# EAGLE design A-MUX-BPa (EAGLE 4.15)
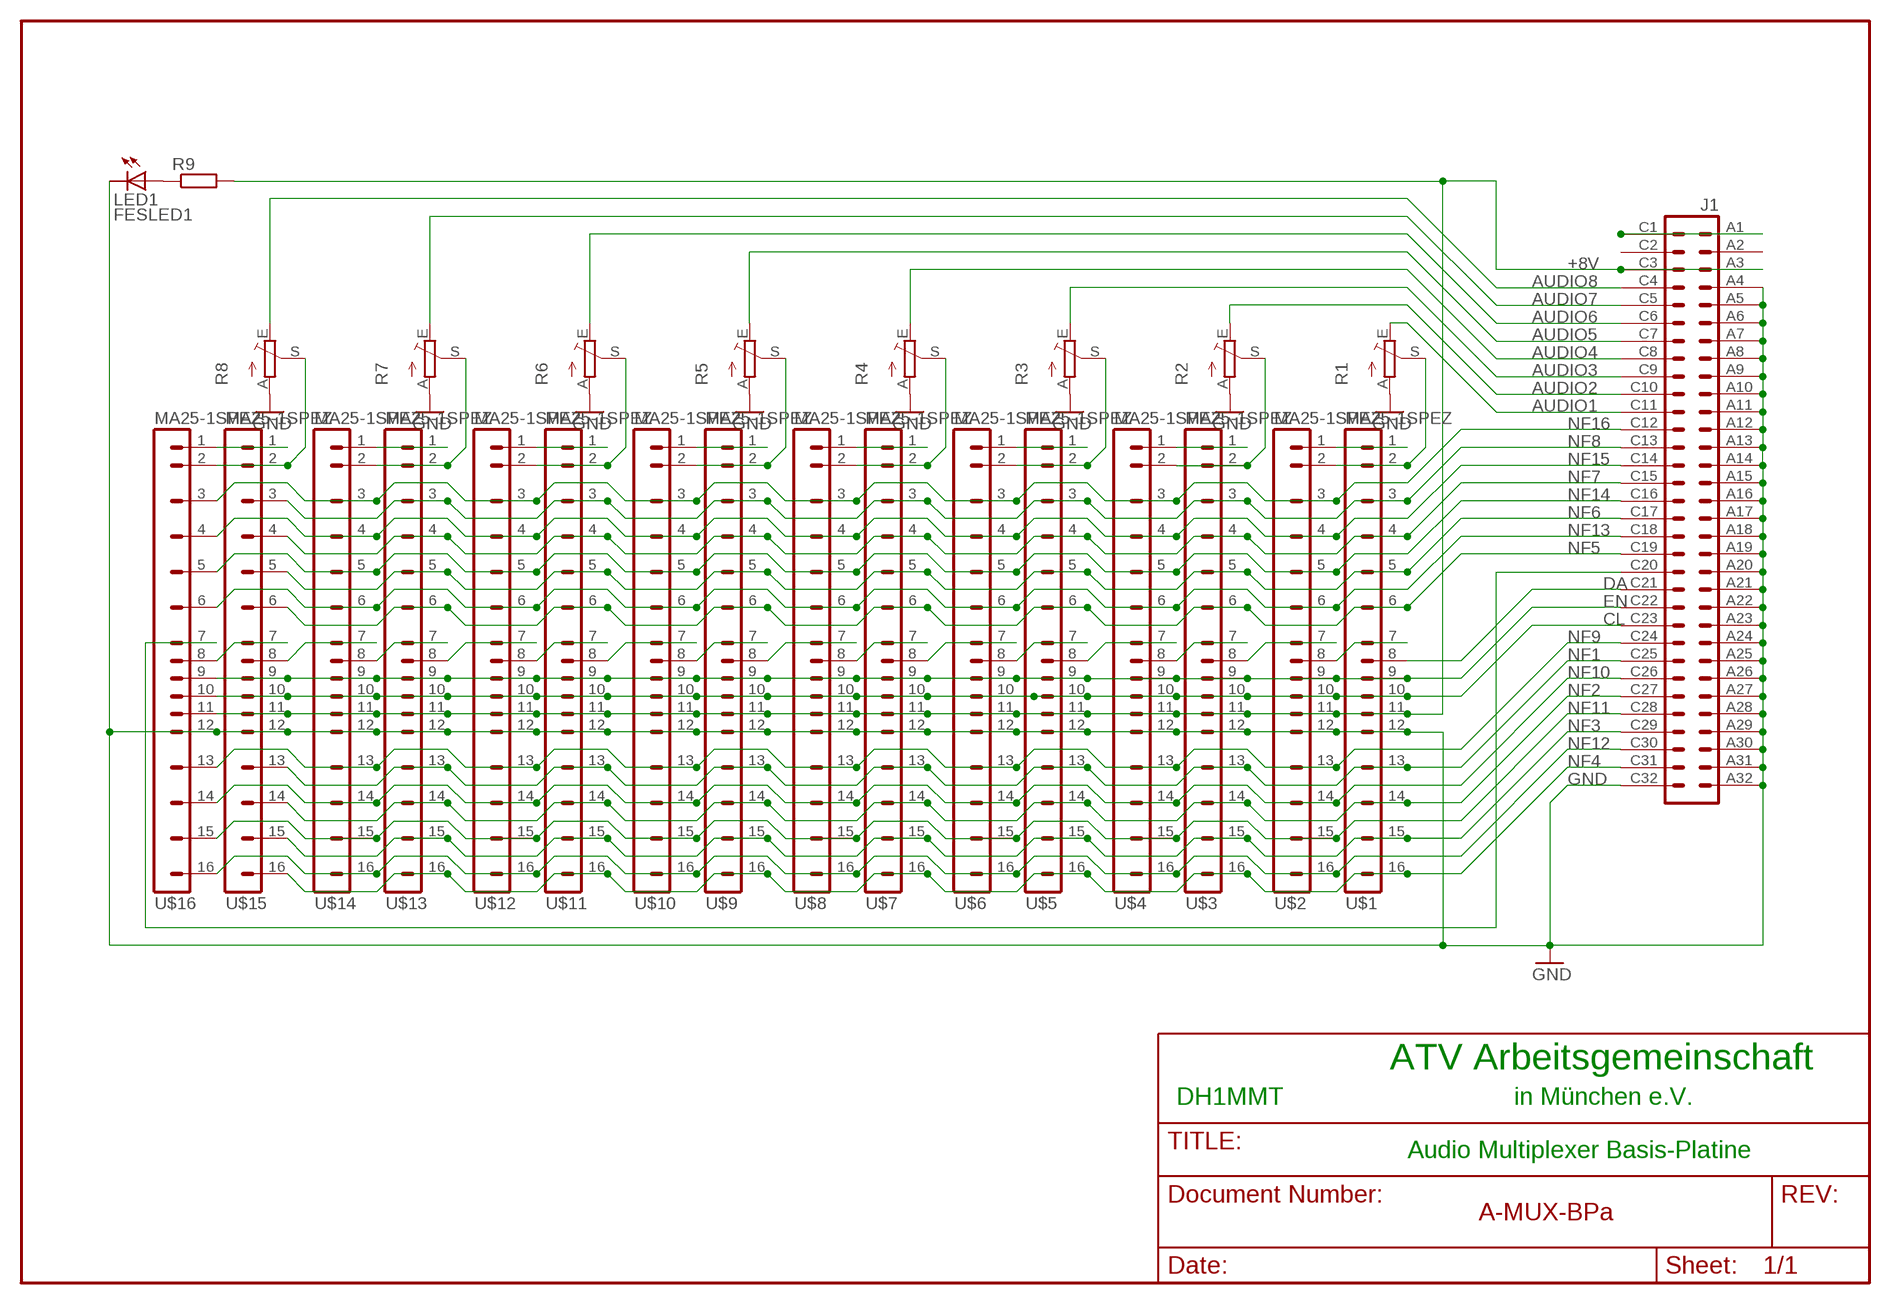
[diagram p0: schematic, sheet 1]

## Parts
J1  VG64  [VG64]
LED1  FESLED1  [FESLED1]
R1  TRIM_EU-B64W  [B64W]
R2  TRIM_EU-B64W  [B64W]
R3  TRIM_EU-B64W  [B64W]
R4  TRIM_EU-B64W  [B64W]
R5  TRIM_EU-B64W  [B64W]
R6  TRIM_EU-B64W  [B64W]
R7  TRIM_EU-B64W  [B64W]
R8  TRIM_EU-B64W  [B64W]
R9  R-EU_0204/7  [0204/7]
U$1  MA25-1SPEZ  [MA25-1SPEZ]
U$2  MA25-1SPEZ  [MA25-1SPEZ]
U$3  MA25-1SPEZ  [MA25-1SPEZ]
U$4  MA25-1SPEZ  [MA25-1SPEZ]
U$5  MA25-1SPEZ  [MA25-1SPEZ]
U$6  MA25-1SPEZ  [MA25-1SPEZ]
U$7  MA25-1SPEZ  [MA25-1SPEZ]
U$8  MA25-1SPEZ  [MA25-1SPEZ]
U$9  MA25-1SPEZ  [MA25-1SPEZ]
U$10  MA25-1SPEZ  [MA25-1SPEZ]
U$11  MA25-1SPEZ  [MA25-1SPEZ]
U$12  MA25-1SPEZ  [MA25-1SPEZ]
U$13  MA25-1SPEZ  [MA25-1SPEZ]
U$14  MA25-1SPEZ  [MA25-1SPEZ]
U$15  MA25-1SPEZ  [MA25-1SPEZ]
U$16  MA25-1SPEZ  [MA25-1SPEZ]

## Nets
+8V: J1.A3 J1.C3 R9.2 U$1.11 U$2.11 U$3.11 U$4.11 U$5.11 U$6.11 U$7.11 U$8.11 U$9.11 U$10.11 U$11.11 U$12.11 U$13.11 U$14.11 U$15.11 U$16.11
+12V: J1.A1 J1.C1
AUDIO1: J1.C11 R1.E
AUDIO2: J1.C10 R2.E
AUDIO3: J1.C9 R3.E
AUDIO4: J1.C8 R4.E
AUDIO5: J1.C7 R5.E
AUDIO6: J1.C6 R6.E
AUDIO7: J1.C5 R7.E
AUDIO8: J1.C4 R8.E
CL: J1.C23 U$1.10 U$2.10 U$3.10 U$4.10 U$5.10 U$6.10 U$7.10 U$8.10 U$9.10 U$10.10 U$11.10 U$12.10 U$13.10 U$14.10 U$15.10 U$16.10
DA: J1.C21 U$1.8
EN: J1.C22 U$1.9 U$2.9 U$3.9 U$4.9 U$5.9 U$6.9 U$7.9 U$8.9 U$9.9 U$10.9 U$11.9 U$12.9 U$13.9 U$14.9 U$15.9 U$16.9
GND: J1.A4 J1.A5 J1.A6 J1.A7 J1.A8 J1.A9 J1.A10 J1.A11 J1.A12 J1.A13 J1.A14 J1.A15 J1.A16 J1.A17 J1.A18 J1.A19 J1.A20 J1.A21 J1.A22 J1.A23 J1.A24 J1.A25 J1.A26 J1.A27 J1.A28 J1.A29 J1.A30 J1.A31 J1.A32 J1.C32 LED1.K(C) R1.A R2.A R3.A R4.A R5.A R6.A R7.A R8.A U$1.12 U$2.12 U$3.12 U$4.12 U$5.12 U$6.12 U$7.12 U$8.12 U$9.12 U$10.12 U$11.12 U$12.12 U$13.12 U$14.12 U$15.12 U$16.12
N$1: J1.C20 U$16.7
N$4: U$1.1 U$2.1
N$5: U$3.1 U$4.1
N$8: U$5.1 U$6.1
N$10: U$7.1 U$8.1
N$11: LED1.A R9.1
N$13: U$15.1 U$16.1
N$15: U$13.1 U$14.1
N$17: U$11.1 U$12.1
N$34: U$9.1 U$10.1
N$35: R5.S U$9.2 U$10.2
N$40: U$1.7 U$2.8
N$43: U$2.7 U$3.8
N$67: U$3.7 U$4.8
N$68: U$4.7 U$5.8
N$69: U$5.7 U$6.8
N$70: U$6.7 U$7.8
N$71: U$7.7 U$8.8
N$72: U$8.7 U$9.8
N$73: U$9.7 U$10.8
N$74: U$10.7 U$11.8
N$75: U$11.7 U$12.8
N$76: U$12.7 U$13.8
N$77: U$13.7 U$14.8
N$78: U$14.7 U$15.8
N$79: U$15.7 U$16.8
N$98: R2.S U$3.2 U$4.2
N$99: R1.S U$1.2 U$2.2
N$103: R3.S U$5.2 U$6.2
N$104: R4.S U$7.2 U$8.2
N$106: R6.S U$11.2 U$12.2
N$107: R7.S U$13.2 U$14.2
N$108: R8.S U$15.2 U$16.2
NF1: J1.C25 U$1.13 U$3.13 U$5.13 U$7.13 U$9.13 U$11.13 U$13.13 U$15.13
NF2: J1.C27 U$1.14 U$3.14 U$5.14 U$7.14 U$9.14 U$11.14 U$13.14 U$15.14
NF3: J1.C29 U$1.15 U$3.15 U$5.15 U$7.15 U$9.15 U$11.15 U$13.15 U$15.15
NF4: J1.C31 U$1.16 U$3.16 U$5.16 U$7.16 U$9.16 U$11.16 U$13.16 U$15.16
NF5: J1.C19 U$1.6 U$3.6 U$5.6 U$7.6 U$9.6 U$11.6 U$13.6 U$15.6
NF6: J1.C17 U$1.5 U$3.5 U$5.5 U$7.5 U$9.5 U$11.5 U$13.5 U$15.5
NF7: J1.C15 U$1.4 U$3.4 U$5.4 U$7.4 U$9.4 U$11.4 U$13.4 U$15.4
NF8: J1.C13 U$1.3 U$3.3 U$5.3 U$7.3 U$9.3 U$11.3 U$13.3 U$15.3
NF9: J1.C24 U$2.13 U$4.13 U$6.13 U$8.13 U$10.13 U$12.13 U$14.13 U$16.13
NF10: J1.C26 U$2.14 U$4.14 U$6.14 U$8.14 U$10.14 U$12.14 U$14.14 U$16.14
NF11: J1.C28 U$2.15 U$4.15 U$6.15 U$8.15 U$10.15 U$12.15 U$14.15 U$16.15
NF12: J1.C30 U$2.16 U$4.16 U$6.16 U$8.16 U$10.16 U$12.16 U$14.16 U$16.16
NF13: J1.C18 U$2.6 U$4.6 U$6.6 U$8.6 U$10.6 U$12.6 U$14.6 U$16.6
NF14: J1.C16 U$2.5 U$4.5 U$6.5 U$8.5 U$10.5 U$12.5 U$14.5 U$16.5
NF15: J1.C14 U$2.4 U$4.4 U$6.4 U$8.4 U$10.4 U$12.4 U$14.4 U$16.4
NF16: J1.C12 U$2.3 U$4.3 U$6.3 U$8.3 U$10.3 U$12.3 U$14.3 U$16.3
Unconnected: J1.A2 J1.C2

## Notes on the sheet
- ATV Arbeitsgemeinschaft
- DH1MMT | in München e.V.
- Audio Multiplexer Basis-Platine

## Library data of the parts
J1 = 19inch:VG64: PCB EUROCARD, 64-pin type C/AC, 2.54 mm
LED1 = led:FESLED1
R1-R8 = pot:TRIM_EU-: POTENTIOMETER
R9 = rcl:R-EU_: RESISTOR, European symbol
U$1-U$16 = con-lstb:MA25-1SPEZ

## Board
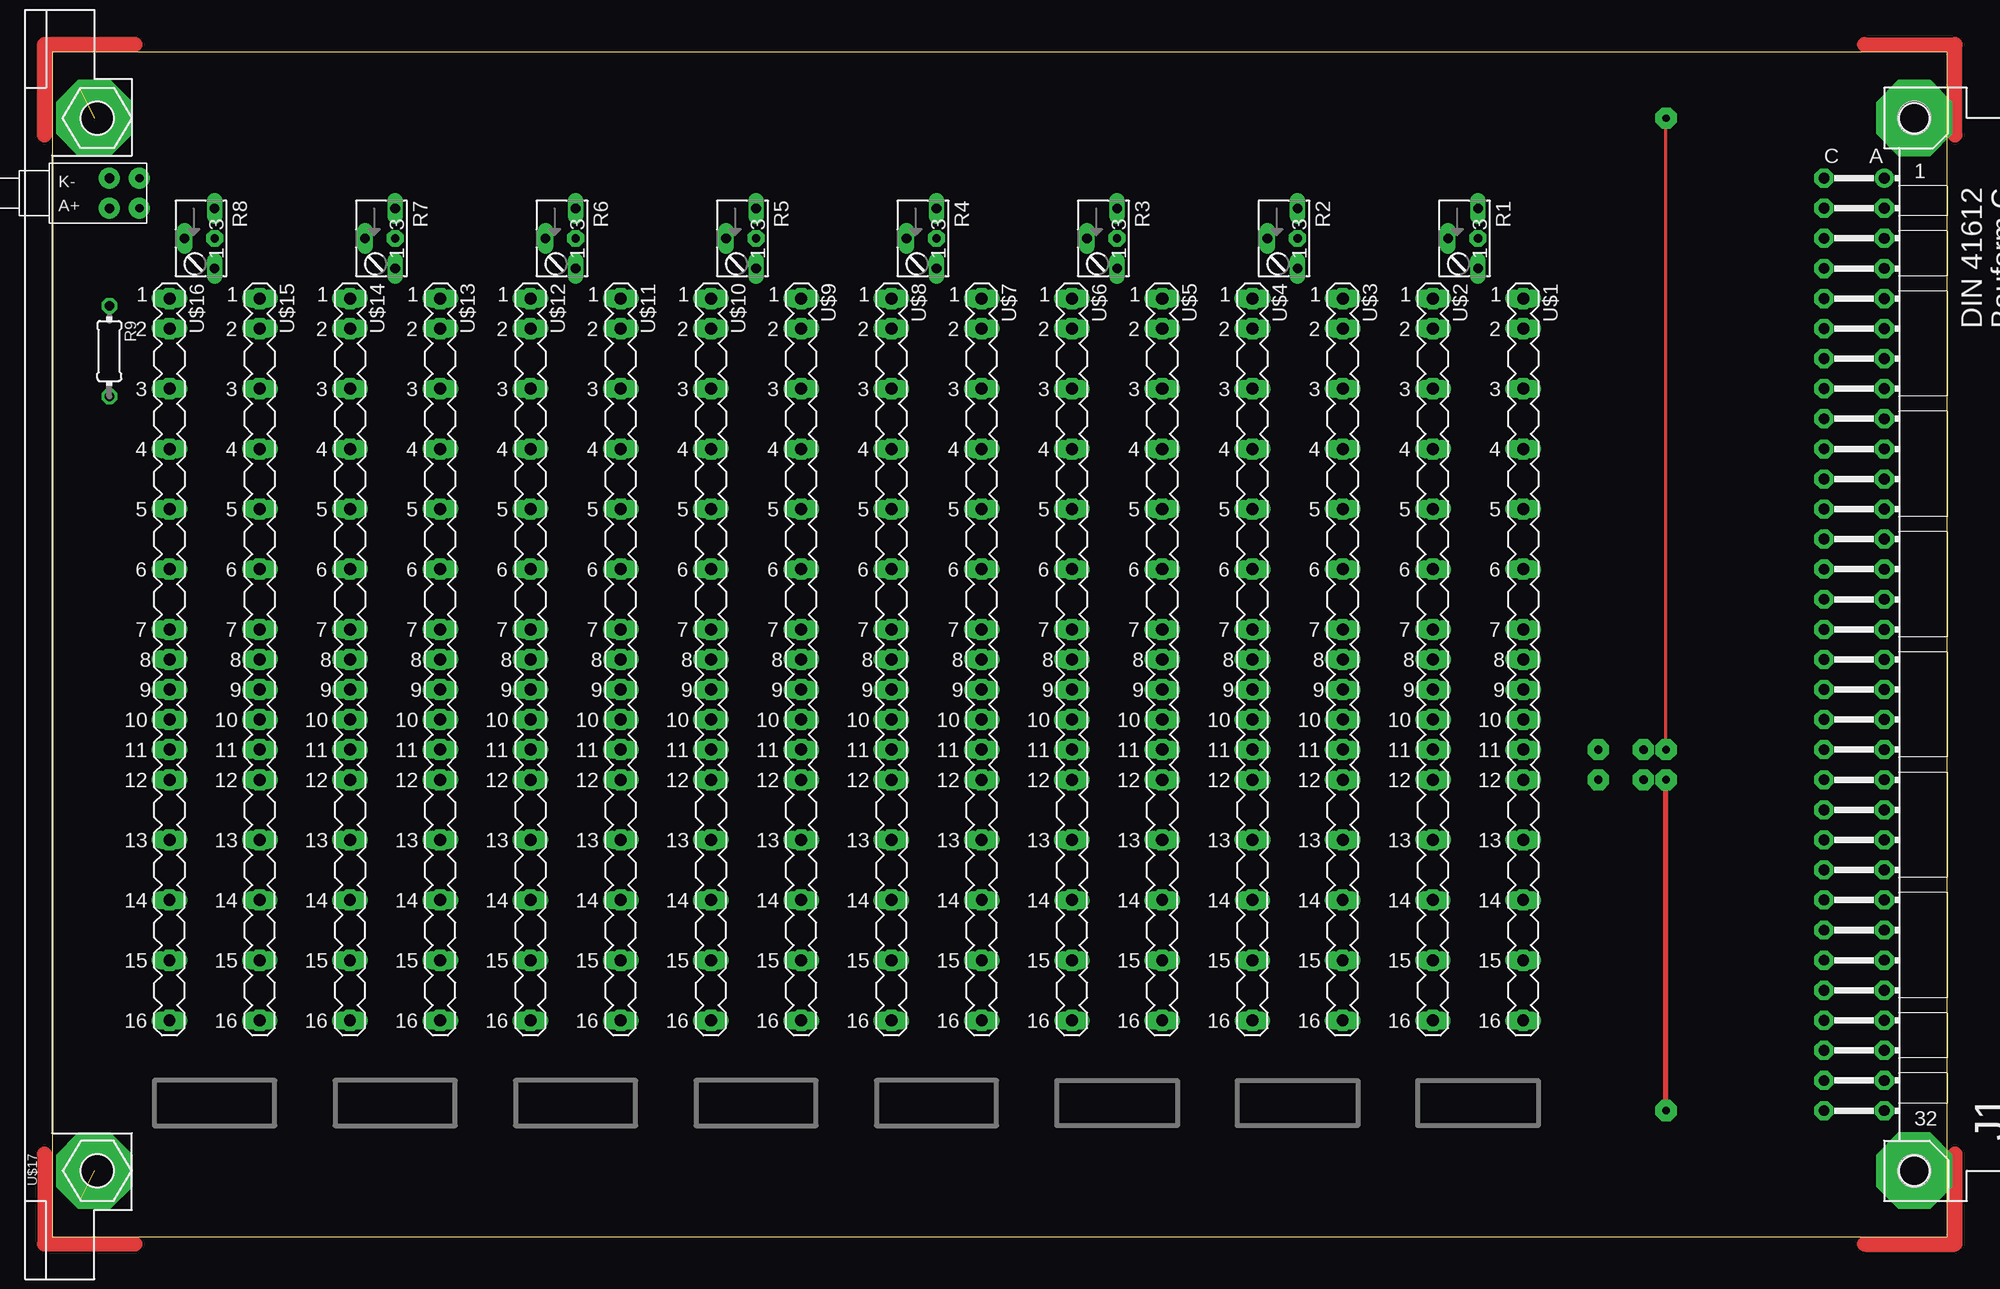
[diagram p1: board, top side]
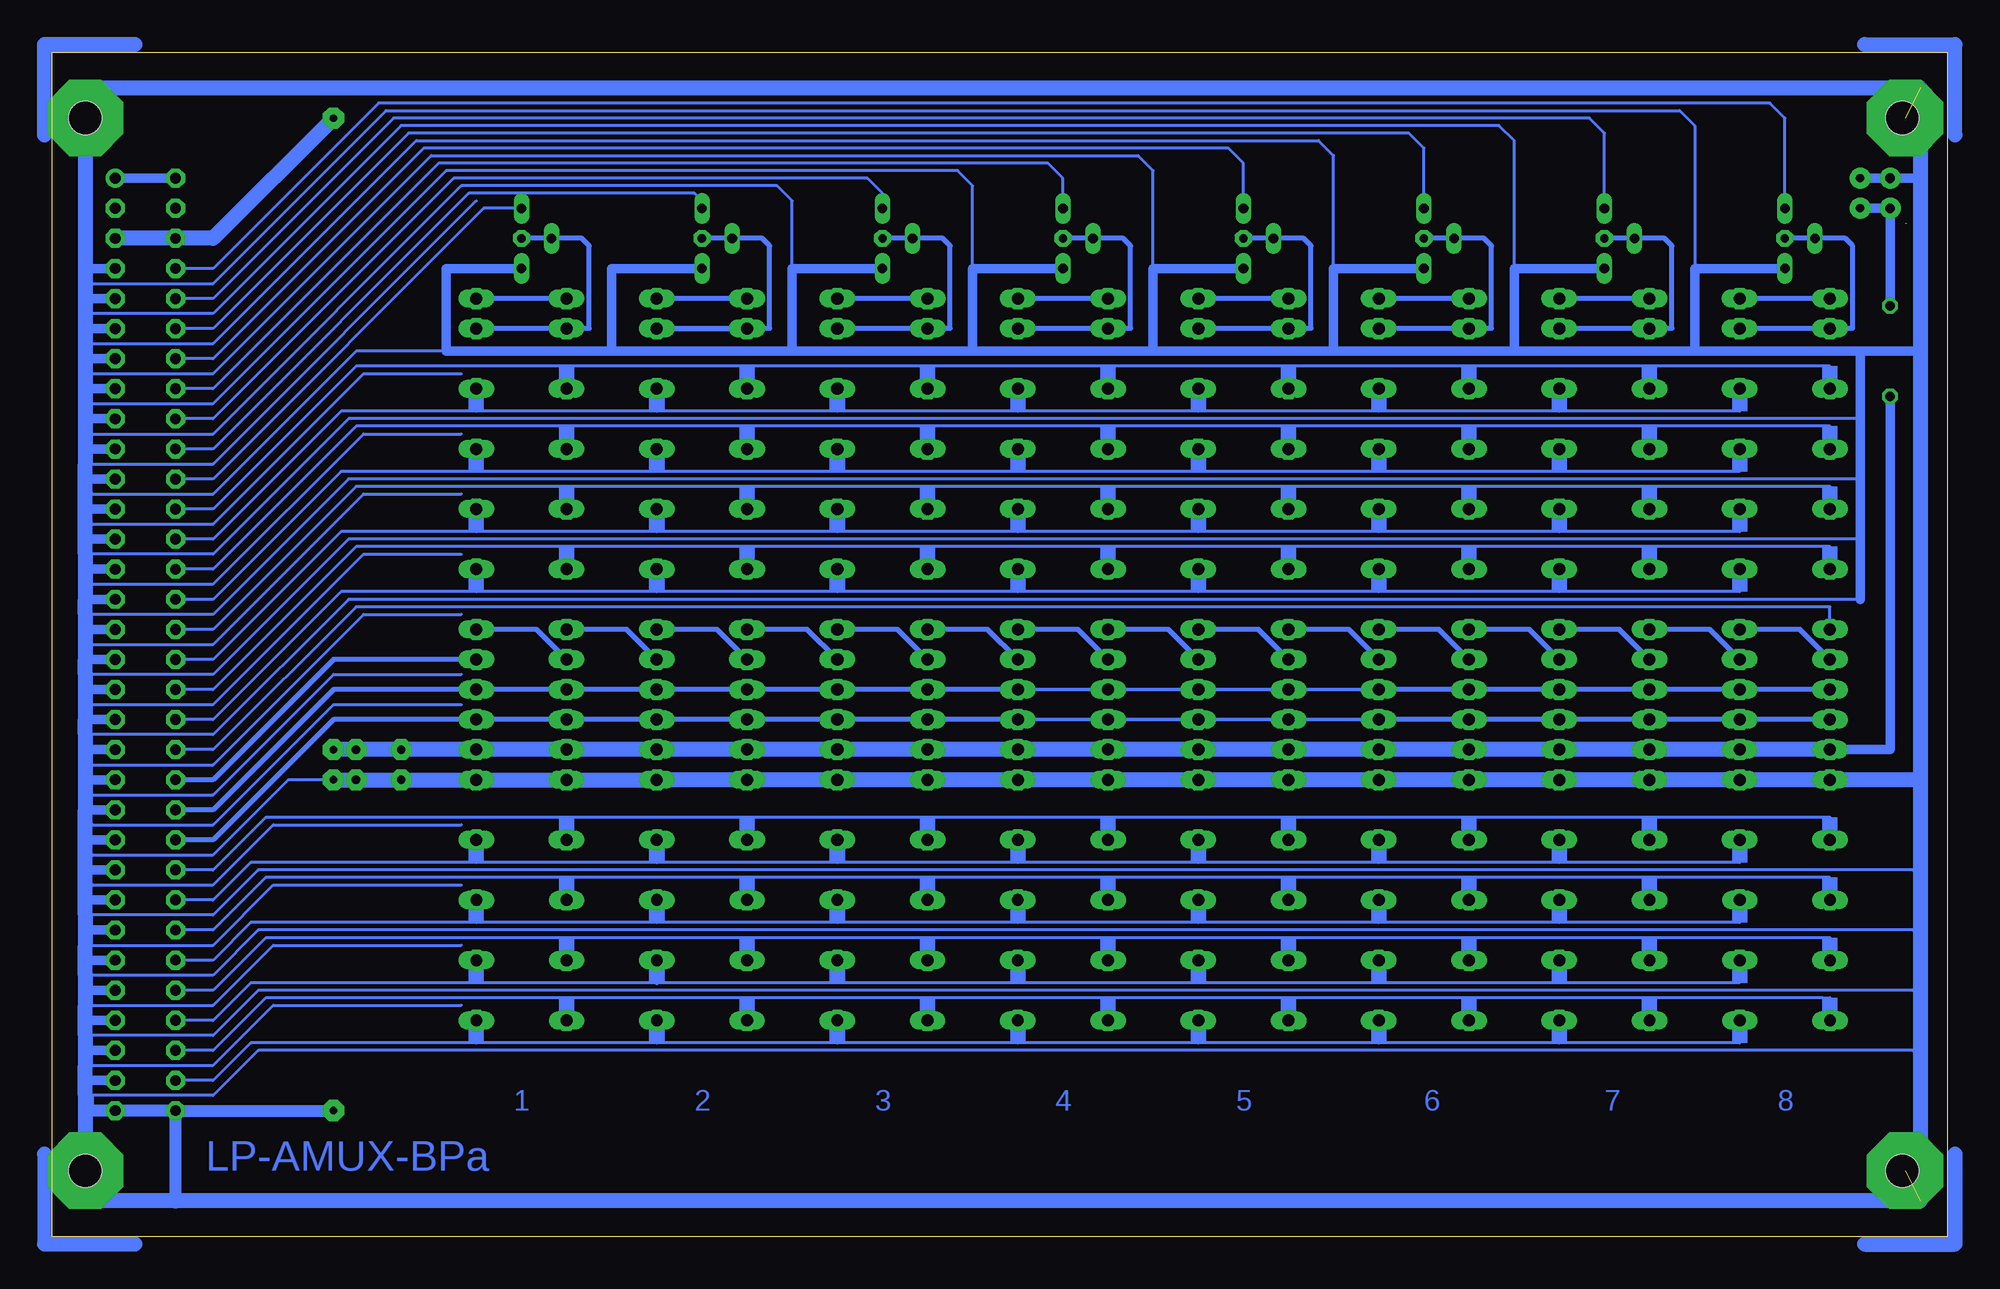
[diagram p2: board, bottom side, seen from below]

Size 160.02 x 100.03 mm. Coordinates in mm from the lower left corner, seen from the top.
Copper layers (1*16): Top 0.035mm / dielectric 1.5mm / Bottom 0.035mm
Design rules "default": minimum track width 10mil, minimum drill 24mil, track to track 8mil, track to pad 8mil, pad to pad 8mil, via to via 8mil, smd to smd 8mil, copper to edge 40mil, drill to drill 8mil, minimum pad ring 10mil, minimum via ring 8mil, stop-mask expansion 4mil, vias tented up to drill 0mil, thermal gap 10mil

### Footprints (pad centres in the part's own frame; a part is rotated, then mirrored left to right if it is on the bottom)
VG64 = drill 0.914 pad 1.6 round: A1 154.94,39.37 | drill 0.914 pad 1.6 octagon: A2 154.94,36.83; A3 154.94,34.29; A4 154.94,31.75; A5 154.94,29.21; A6 154.94,26.67; A7 154.94,24.13; A8 154.94,21.59; A9 154.94,19.05; A10 154.94,16.51; A11 154.94,13.97; A12 154.94,11.43; A13 154.94,8.89; A14 154.94,6.35; A15 154.94,3.81; A16 154.94,1.27; A17 154.94,-1.27; A18 154.94,-3.81; A19 154.94,-6.35; A20 154.94,-8.89; A21 154.94,-11.43; A22 154.94,-13.97; A23 154.94,-16.51; A24 154.94,-19.05; A25 154.94,-21.59; A26 154.94,-24.13; A27 154.94,-26.67; A28 154.94,-29.21; A29 154.94,-31.75; A30 154.94,-34.29; A31 154.94,-36.83; A32 154.94,-39.37; C1 149.86,39.37; C2 149.86,36.83; C3 149.86,34.29; C4 149.86,31.75; C5 149.86,29.21; C6 149.86,26.67; C7 149.86,24.13; C8 149.86,21.59; C9 149.86,19.05; C10 149.86,16.51; C11 149.86,13.97; C12 149.86,11.43; C13 149.86,8.89; C14 149.86,6.35; C15 149.86,3.81; C16 149.86,1.27; C17 149.86,-1.27; C18 149.86,-3.81; C19 149.86,-6.35; C20 149.86,-8.89; C21 149.86,-11.43; C22 149.86,-13.97; C23 149.86,-16.51; C24 149.86,-19.05; C25 149.86,-21.59; C26 149.86,-24.13; C27 149.86,-26.67; C28 149.86,-29.21; C29 149.86,-31.75; C30 149.86,-34.29; C31 149.86,-36.83; C32 149.86,-39.37 | hole 2.794: 157.48,44.45; 157.48,-44.45
FESLED1 = drill 0.813 pad 1.778 round: A 5.08,-1.27; A1 5.08,-1.27; K 5.08,1.27; K1 5.08,1.27
B64W = drill 0.813 long: A 2.54,0; E -2.54,0; S 0,-2.54
0204/7 = drill 0.813 octagon: 1 -3.81,0; 2 3.81,0
MA25-1SPEZ = drill 1.016 long: 1 0,27.94; 2 0,25.4; 3 0,20.32; 4 0,15.24; 5 0,10.16; 6 0,5.08; 7 0,0; 8 0,-2.54; 9 0,-5.08; 10 0,-7.62; 11 0,-10.16; 12 0,-12.7; 13 0,-17.78 | drill 1 long: 14 0,-22.86; 15 0,-27.94; 16 0,-33.02
FPH = hole 2.794: 3.81,44.45; 3.81,-44.45

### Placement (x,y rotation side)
E$1  [DINA4_L]  not placed on the board
J1  -0.25,50.01 0 top
LED1  -0.25,88.11 0 top
R1  120.4,84.3 270 top
R2  105.16,84.3 270 top
R3  89.92,84.3 270 top
R4  74.68,84.3 270 top
R5  59.44,84.3 270 top
R6  44.2,84.3 270 top
R7  28.96,84.3 270 top
R8  13.72,84.3 270 top
R9  4.83,74.78 270 top
U$1  124.21,51.28 0 top
U$2  116.59,51.28 0 top
U$3  108.97,51.28 0 top
U$4  101.35,51.28 0 top
U$5  93.73,51.28 0 top
U$6  86.11,51.28 0 top
U$7  78.49,51.28 0 top
U$8  70.87,51.28 0 top
U$9  63.25,51.28 0 top
U$10  55.63,51.28 0 top
U$11  48.01,51.28 0 top
U$12  40.39,51.28 0 top
U$13  32.77,51.28 0 top
U$14  25.15,51.28 0 top
U$15  17.53,51.28 0 top
U$16  9.91,51.28 0 top
U$17  [FPH]  0,50.01 0 top

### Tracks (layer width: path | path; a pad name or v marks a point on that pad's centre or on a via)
+8V  (via drill 0.6 pad 1.78, 0.7 pad 1.78, 0.9 pad 1.78)
  Top 0.254: v136.27,41.12 v136.27,94.46
  Bottom 0.813: U$16.11 4.83,41.12 R9.2
  Bottom 1.27: J1.A3 J1.C3 146.43,84.3 v136.27,94.46 | U$16.11 U$15.11 U$14.11 U$13.11 U$12.11 U$11.11 U$10.11 U$9.11 U$8.11 U$7.11 U$6.11 U$5.11 U$4.11 U$3.11 U$2.11 U$1.11 v130.56,41.12 v134.37,41.12 v136.27,41.12
  other vias: 78.49,41.12 86.11,41.12 93.73,41.12 124.21,41.12 116.59,41.12 101.35,41.12 108.97,41.12 9.91,41.12 17.53,41.12 25.15,41.12 32.77,41.12 40.39,41.12 48.01,41.12
+12V
  Bottom 0.813: J1.C1 J1.A1
AUDIO1
  Bottom 0.254: J1.C11 146.43,63.98 123.57,86.84 R1.E
AUDIO2
  Bottom 0.254: J1.C10 146.43,66.52 124.84,88.11 105.79,88.11 105.16,87.48 R2.E
AUDIO3
  Bottom 0.254: J1.C9 146.43,69.06 126.11,89.38 91.19,89.38 89.92,88.11 R3.E
AUDIO4
  Bottom 0.254: J1.C8 146.43,71.6 127.38,90.65 75.95,90.65 74.68,89.38 R4.E
AUDIO5
  Bottom 0.254: J1.C7 146.43,74.14 128.65,91.92 60.71,91.92 59.44,90.65 R5.E
AUDIO6
  Bottom 0.254: J1.C6 146.43,76.68 129.92,93.19 45.47,93.19 44.2,91.92 R6.E
AUDIO7
  Bottom 0.254: R7.E 28.96,93.19 30.23,94.46 131.19,94.46 146.43,79.22 J1.C5
AUDIO8
  Bottom 0.254: J1.C4 146.43,81.76 132.46,95.73 14.99,95.73 13.72,94.46 R8.E
CL
  Bottom 0.305: U$7.10 U$8.10 U$9.10 U$10.10 U$11.10
  Bottom 0.406: J1.C23 146.43,33.5 136.27,43.66 U$1.10 U$2.10 U$3.10 U$4.10 U$5.10 U$6.10 U$7.10 | U$11.10 U$12.10 U$13.10 U$14.10 U$15.10 U$16.10
DA  (via drill 0.9 pad 1.78)
  Bottom 0.406: U$1.8 136.27,48.74 146.43,38.58 J1.C21
  other vias: 124.21,48.74
EN  (via drill 0.9 pad 1.78)
  Bottom 0.305: U$7.9 U$8.9 U$9.9 U$10.9 U$11.9
  Bottom 0.406: J1.C22 146.43,36.04 136.27,46.2 U$1.9 U$2.9 U$3.9 U$4.9 U$5.9 U$6.9 U$7.9 | U$11.9 U$12.9 U$13.9 U$14.9 U$15.9 U$16.9
  other vias: 124.21,46.2 116.59,46.2 108.97,46.2 93.73,46.2 101.35,46.2
GND  (via drill 0.6 pad 1.78, 0.6 pad 6.45, 0.7 pad 1.78, 0.9 pad 1.78)  (2 unrouted)
  Top 0.406: v136.27,10.64 v136.27,38.58
  Bottom 0.254: 157.23,80.49 146.43,80.49 131.83,95.1 22.61,95.1 21.34,93.83 21.34,81.76 | 157.23,75.41 146.43,75.41 129.29,92.56 53.09,92.56 51.82,91.29 51.82,81.76 | 67.06,81.76 67.06,90.02 68.33,91.29 128.02,91.29 146.43,72.87 157.23,72.87 157.23,70.33 146.43,70.33 126.75,90.02 83.57,90.02 82.3,88.75 82.3,81.76 | 157.23,67.79 146.43,67.79 125.48,88.75 98.81,88.75 97.54,87.48 97.54,81.76 | 157.23,62.71 146.43,62.71 134.37,74.78 126.75,74.78 | 36.58,81.76 36.58,92.56 37.85,93.83 130.56,93.83 146.43,77.95 156.59,77.95 | 157.23,57.63 146.43,57.63 135,69.06 7.37,69.06 | 157.23,52.55 146.43,52.55 135,63.98 7.37,63.98 | 157.23,47.47 146.43,47.47 135,58.9 7.37,58.9 | 7.37,53.82 135,53.82 146.43,42.39 157.23,42.39 | 157.23,32.23 146.43,32.23 140.08,38.58 v136.27,38.58 | 157.23,27.15 146.43,27.15 142.62,30.96 2.29,30.96 | 2.29,25.88 142.62,25.88 146.43,22.07 157.23,22.07 | 157.23,16.99 146.43,16.99 142.62,20.8 2.29,20.8 | 157.23,65.25 146.43,65.25 124.21,87.48 | 156.59,10.64 156.59,11.91 | 157.23,60.17 146.43,60.17 133.73,72.87 125.48,72.87 | 157.23,55.09 146.43,55.09 133.73,67.79 125.48,67.79 | 157.23,50.01 146.43,50.01 133.73,62.71 125.48,62.71 | 157.23,44.93 146.43,44.93 133.73,57.63 125.48,57.63 | 157.23,39.85 146.43,39.85 133.73,52.55 125.48,52.55 | 157.23,37.31 146.43,37.31 136.27,47.47 125.48,47.47 | 157.23,34.77 146.43,34.77 136.27,44.93 125.48,44.93 | 157.23,24.61 146.43,24.61 141.35,29.69 125.48,29.69 | 157.23,19.53 146.43,19.53 141.35,24.61 125.48,24.61 | 157.23,14.45 146.43,14.45 141.35,19.53 125.48,19.53 | 157.23,11.91 146.43,11.91 142.62,15.72 2.29,15.72 | 157.23,29.69 146.43,29.69 141.35,34.77 125.48,34.77
  Bottom 0.813: 157.23,46.2 J1.A18 | 157.23,48.74 J1.A17 | 157.23,51.28 J1.A16 | 157.23,43.66 J1.A19 | 157.23,41.12 J1.A20 | 157.23,53.82 J1.A15 | 157.23,56.36 J1.A14 | 157.23,38.58 J1.A21 | 157.23,36.04 J1.A22 | 157.23,58.9 J1.A13 | 157.23,61.44 J1.A12 | 157.23,33.5 J1.A23 | 157.23,30.96 J1.A24 | 157.23,63.98 J1.A11 | 157.23,66.52 J1.A10 | 157.23,28.42 J1.A25 | 157.23,25.88 J1.A26 | 157.23,69.06 J1.A9 | 157.23,71.6 J1.A8 | 157.23,23.34 J1.A27 | 157.23,20.8 J1.A28 | 157.23,74.14 J1.A7 | 157.23,76.68 J1.A6 | 157.23,18.26 J1.A29 | 157.23,15.72 J1.A30 | 157.23,79.22 J1.A5 | 157.23,81.76 J1.A4 | 157.23,13.18 J1.A31 | 21.34,74.78 21.34,81.76 R8.A | 51.82,74.78 51.82,81.76 R6.A | 67.06,74.78 67.06,81.76 R5.A | 82.3,74.78 82.3,81.76 R4.A | 97.54,74.78 97.54,81.76 R3.A | 112.78,74.78 126.75,74.78 126.75,81.76 R1.A | 97.54,74.78 112.78,74.78 | 82.3,74.78 97.54,74.78 | 67.06,74.78 82.3,74.78 | 51.82,74.78 67.06,74.78 | 36.58,74.78 36.58,81.76 R7.A | 36.58,74.78 51.82,74.78 | 21.34,74.78 36.58,74.78 | 7.37,74.78 7.37,69.06 7.37,63.98 7.37,58.9 7.37,53.82 | 7.37,74.78 21.34,74.78 | 112.78,74.78 112.78,81.76 R2.A | 2.29,89.38 LED1.K v7.37,89.38 | 2.29,74.78 7.37,74.78
  Bottom 1.016: J1.C32 J1.A32 156.59,10.64 157.23,10.64 | 149.61,3.02 J1.C32 | J1.C32 v136.27,10.64
  Bottom 1.27: 2.29,38.58 2.29,74.78 2.29,89.38 2.29,97 157.23,97 v157.23,94.46 157.23,81.76 157.23,80.49 157.23,79.22 157.23,76.68 157.23,75.41 157.23,74.14 157.23,72.87 157.23,71.6 157.23,70.33 157.23,69.06 157.23,67.79 157.23,66.52 157.23,65.25 157.23,63.98 157.23,62.71 157.23,61.44 157.23,60.17 157.23,58.9 157.23,57.63 157.23,56.36 157.23,55.09 157.23,53.82 157.23,52.55 157.23,51.28 157.23,50.01 157.23,48.74 157.23,47.47 157.23,46.2 157.23,44.93 157.23,43.66 157.23,42.39 157.23,41.12 157.23,39.85 157.23,38.58 157.23,37.31 157.23,36.04 157.23,34.77 157.23,33.5 157.23,32.23 157.23,30.96 157.23,29.69 157.23,28.42 157.23,27.15 157.23,25.88 157.23,24.61 157.23,23.34 157.23,22.07 157.23,20.8 157.23,19.53 157.23,18.26 157.23,16.99 157.23,15.72 157.23,14.45 157.23,13.18 157.23,11.91 157.23,10.64 v157.23,5.56 157.23,3.02 149.61,3.02 2.29,3.02 2.29,15.72 2.29,20.8 2.29,25.88 2.29,30.96 2.29,38.58 | v136.27,38.58 v134.37,38.58 v130.56,38.58 U$1.12 U$2.12 U$3.12 U$4.12 U$5.12 U$6.12 U$7.12 U$8.12 U$9.12 U$10.12 U$11.12 U$12.12 U$13.12 U$14.12 U$15.12 U$16.12 2.29,38.58
  other vias: 124.21,38.58 116.59,38.58 108.97,38.58 101.35,38.58 93.73,38.58 86.11,38.58 78.49,38.58 48.01,38.58 40.39,38.58 32.77,38.58 25.15,38.58 17.53,38.58 9.91,38.58 70.87,38.58 63.25,38.58 3.56,94.46 3.56,5.56
N$1  (via drill 0.9 pad 1.78)
  Bottom 0.254: U$16.7 9.91,53.19 134.37,53.19 146.43,41.12 J1.C20
  other vias: 9.91,51.28
N$2
  Bottom 0: 3.56,85.57 3.43,85.57
N$4
  Bottom 0.254: U$2.1 U$1.1
N$5
  Bottom 0.254: U$4.1 U$3.1
N$8
  Bottom 0.254: U$6.1 U$5.1
N$10
  Bottom 0.254: U$8.1 U$7.1
N$11  (via drill 0.7 pad 1.78)
  Bottom 0.813: R9.1 LED1.A v7.37,86.84
N$13
  Bottom 0.254: U$16.1 U$15.1
N$15
  Bottom 0.406: U$14.1 U$13.1
N$17
  Bottom 0.254: U$12.1 U$11.1
N$18  (via drill 0.9 pad 1.78)
  other vias: 63.25,41.12
N$19  (via drill 0.9 pad 1.78)
  other vias: 70.87,43.66
N$20  (via drill 0.9 pad 1.78)
  other vias: 78.49,46.2
N$21  (via drill 0.9 pad 1.78)
  other vias: 55.63,23.34
N$24  (via drill 0.9 pad 1.78)
  other vias: 63.25,28.42
N$25  (via drill 0.9 pad 1.78)
  other vias: 108.97,43.66
N$26  (via drill 0.9 pad 1.78)
  other vias: 116.59,43.66
N$27  (via drill 0.9 pad 1.78)
  other vias: 70.87,28.42
N$28  (via drill 0.9 pad 1.78)
  other vias: 70.87,23.34
N$29  (via drill 0.9 pad 1.78)
  other vias: 70.87,18.26
N$30  (via drill 0.9 pad 1.78)
  other vias: 55.63,18.26
N$31  (via drill 0.9 pad 1.78)
  other vias: 124.21,43.66
N$32  (via drill 0.9 pad 1.78)
  other vias: 101.35,43.66
N$33  (via drill 0.9 pad 1.78)
  other vias: 93.73,43.66
N$34
  Bottom 0.254: U$10.1 U$9.1
N$35  (via drill 0.7 pad 1.42)
  Bottom 0.406: U$9.2 U$10.2 53.72,76.68 53.72,83.67 54.36,84.3 R5.S v59.44,84.3
N$36  (via drill 0.9 pad 1.78)
  other vias: 86.11,46.2
N$37  (via drill 0.9 pad 1.78)
  other vias: 86.11,43.66
N$38  (via drill 0.9 pad 1.78)
  other vias: 78.49,43.66
N$39  (via drill 0.9 pad 1.78)
  other vias: 70.87,33.5
N$40
  Bottom 0.406: U$1.7 119.13,51.28 U$2.8
N$41  (via drill 0.9 pad 1.78)
  other vias: 70.87,41.12
N$42  (via drill 0.9 pad 1.78)
  other vias: 70.87,46.2
N$43
  Bottom 0.406: U$2.7 111.51,51.28 U$3.8
N$44  (via drill 0.9 pad 1.78)
  other vias: 63.25,46.2
N$45  (via drill 0.9 pad 1.78)
  other vias: 63.25,43.66
N$46  (via drill 0.9 pad 1.78)
  other vias: 48.01,46.2
N$47  (via drill 0.9 pad 1.78)
  other vias: 48.01,43.66
N$49  (via drill 0.9 pad 1.78)
  other vias: 55.63,41.12
N$50  (via drill 0.9 pad 1.78)
  other vias: 55.63,46.2
N$51  (via drill 0.9 pad 1.78)
  other vias: 55.63,43.66
N$52  (via drill 0.9 pad 1.78)
  other vias: 40.39,46.2
N$53  (via drill 0.9 pad 1.78)
  other vias: 40.39,43.66
N$54  (via drill 0.9 pad 1.78)
  other vias: 32.77,46.2
N$55  (via drill 0.9 pad 1.78)
  other vias: 32.77,43.66
N$56  (via drill 0.9 pad 1.78)
  other vias: 9.91,46.2
N$57  (via drill 0.9 pad 1.78)
  other vias: 9.91,43.66
N$58  (via drill 0.9 pad 1.78)
  other vias: 17.53,46.2
N$59  (via drill 0.9 pad 1.78)
  other vias: 17.53,43.66
N$60  (via drill 0.9 pad 1.78)
  other vias: 25.15,46.2
N$61  (via drill 0.9 pad 1.78)
  other vias: 25.15,43.66
N$62  (via drill 0.9 pad 1.78)
  other vias: 55.63,38.58
N$63  (via drill 0.9 pad 1.78)
  other vias: 70.87,66.52
N$64  (via drill 0.9 pad 1.78)
  other vias: 70.87,61.44
N$65  (via drill 0.9 pad 1.78)
  other vias: 70.87,56.36
N$66  (via drill 0.9 pad 1.78)
  other vias: 70.87,71.6
N$67
  Bottom 0.406: U$3.7 103.89,51.28 U$4.8
N$68
  Bottom 0.406: U$4.7 96.27,51.28 U$5.8
N$69
  Bottom 0.406: U$5.7 88.65,51.28 U$6.8
N$70
  Bottom 0.406: U$6.7 81.03,51.28 U$7.8
N$71
  Bottom 0.406: U$7.7 73.41,51.28 U$8.8
N$72
  Bottom 0.406: U$8.7 65.79,51.28 U$9.8
N$73
  Bottom 0.406: U$9.7 58.17,51.28 U$10.8
N$74
  Bottom 0.406: U$10.7 50.55,51.28 U$11.8
N$75
  Bottom 0.406: U$11.7 42.93,51.28 U$12.8
N$76
  Bottom 0.406: U$12.7 35.31,51.28 U$13.8
N$77
  Bottom 0.406: U$13.7 27.69,51.28 U$14.8
N$78
  Bottom 0.406: U$14.7 20.07,51.28 U$15.8
N$79
  Bottom 0.406: U$15.7 12.45,51.28 U$16.8
N$80  (via drill 0.9 pad 1.78)
  other vias: 124.21,76.68
N$82  (via drill 0.9 pad 1.78)
  other vias: 116.59,76.68
N$83  (via drill 0.9 pad 1.78)
  other vias: 108.97,76.68
N$84  (via drill 0.9 pad 1.78)
  other vias: 101.35,76.68
N$85  (via drill 0.9 pad 1.78)
  other vias: 93.73,76.68
N$86  (via drill 0.9 pad 1.78)
  other vias: 86.11,76.68
N$87  (via drill 0.9 pad 1.78)
  other vias: 78.49,76.68
N$88  (via drill 0.9 pad 1.78)
  other vias: 70.87,76.68
N$89  (via drill 0.9 pad 1.78)
  other vias: 63.25,76.68
N$90  (via drill 0.9 pad 1.78)
  other vias: 55.63,76.68
N$91  (via drill 0.9 pad 1.78)
  other vias: 48.01,76.68
N$92  (via drill 0.9 pad 1.78)
  other vias: 40.39,76.68
N$93  (via drill 0.9 pad 1.78)
  other vias: 32.77,76.68
N$94  (via drill 0.9 pad 1.78)
  other vias: 25.15,76.68
N$96  (via drill 0.9 pad 1.78)
  other vias: 17.53,76.68
N$97  (via drill 0.9 pad 1.78)
  other vias: 9.91,76.68
N$98  (via drill 0.7 pad 1.42)
  Bottom 0.406: U$4.2 U$3.2 99.44,76.68 99.44,83.67 100.08,84.3 R2.S v105.16,84.3
N$99  (via drill 0.7 pad 1.42)
  Bottom 0.406: U$1.2 U$2.2 114.68,76.68 114.68,83.67 115.32,84.3 R1.S | R1.S v120.4,84.3 R1.S
N$103  (via drill 0.7 pad 1.42)
  Bottom 0.406: U$5.2 U$6.2 84.2,76.68 84.2,83.67 84.84,84.3 R3.S v89.92,84.3
N$104  (via drill 0.7 pad 1.42)
  Bottom 0.406: U$7.2 U$8.2 68.96,76.68 68.96,83.67 69.6,84.3 R4.S v74.68,84.3
N$106  (via drill 0.7 pad 1.42)
  Bottom 0.406: U$11.2 U$12.2 38.48,76.68 38.48,83.67 39.12,84.3 R6.S v44.2,84.3
N$107  (via drill 0.7 pad 1.42)
  Bottom 0.406: U$13.2 U$14.2 23.24,76.68 23.24,83.67 23.88,84.3 R7.S v28.96,84.3
N$108  (via drill 0.7 pad 1.42)
  Bottom 0.406: U$15.2 U$16.2 8,76.68 8,83.67 8.64,84.3 R8.S v13.72,84.3
NF1  (via drill 0.9 pad 1.78)
  Bottom 0.254: U$15.13 17.53,31.6 32.77,31.6 | 32.77,31.6 U$13.13 | 48.01,31.6 U$11.13 | 32.77,31.6 48.01,31.6 | 63.25,31.6 U$9.13 | 48.01,31.6 63.25,31.6 | 78.49,31.6 U$7.13 | 63.25,31.6 78.49,31.6 | 124.21,31.6 U$1.13 | 93.73,31.6 U$5.13 | 78.49,31.6 93.73,31.6 | 93.73,31.6 108.97,31.6 | 108.97,31.6 124.21,31.6 | 108.97,31.6 U$3.13 | 124.21,31.6 143.26,31.6 146.43,28.42 J1.C25
  other vias: 17.53,33.5 32.77,33.5 48.01,33.5 63.25,33.5 78.49,33.5 93.73,33.5 124.21,33.5 108.97,33.5
NF2  (via drill 0.9 pad 1.78)
  Bottom 0.254: U$15.14 17.53,26.52 32.77,26.52 | 32.77,26.52 U$13.14 | 48.01,26.52 U$11.14 | 32.77,26.52 48.01,26.52 | 63.25,26.52 U$9.14 | 48.01,26.52 63.25,26.52 | 78.49,26.52 U$7.14 | 63.25,26.52 78.49,26.52 | 93.73,26.52 U$5.14 | 78.49,26.52 93.73,26.52 | 108.97,26.52 U$3.14 | 93.73,26.52 108.97,26.52 | 108.97,26.52 124.21,26.52 | 124.21,26.52 U$1.14 | 124.21,26.52 143.26,26.52 146.43,23.34 J1.C27
  other vias: 17.53,28.42 32.77,28.42 48.01,28.42 78.49,28.42 93.73,28.42 108.97,28.42 124.21,28.42
NF3  (via drill 0.9 pad 1.78)
  Bottom 0.254: 32.77,21.44 17.53,21.44 U$15.15 | 32.77,21.44 48.01,21.44 | 63.25,21.44 U$9.15 | 48.01,21.44 63.25,21.44 | 78.49,21.44 U$7.15 | 63.25,21.44 78.49,21.44 | 93.73,21.44 U$5.15 | 78.49,21.44 93.73,21.44 | 93.73,21.44 108.97,21.44 124.21,21.44 | 124.21,21.44 U$1.15 | 124.21,21.44 143.26,21.44 146.43,18.26 J1.C29 | 48.01,21.44 U$11.15 | 32.77,21.44 U$13.15
  Bottom 0.406: 108.97,21.44 U$3.15
  other vias: 63.25,23.34 78.49,23.34 93.73,23.34 108.97,23.34 124.21,23.34 17.53,23.34 32.77,23.34 48.01,23.34
NF4  (via drill 0.9 pad 1.78)
  Bottom 0.254: 32.77,16.36 17.53,16.36 U$15.16 | 32.77,16.36 48.01,16.36 | 63.25,16.36 U$9.16 | 48.01,16.36 63.25,16.36 | 78.49,16.36 U$7.16 | 63.25,16.36 78.49,16.36 | 93.73,16.36 U$5.16 | 78.49,16.36 93.73,16.36 | 108.97,16.36 U$3.16 | 93.73,16.36 108.97,16.36 | 108.97,16.36 124.21,16.36 | 124.21,16.36 U$1.16 | 124.21,16.36 143.26,16.36 146.43,13.18 J1.C31 | 48.01,16.36 U$11.16 | 32.77,16.36 U$13.16
  other vias: 63.25,18.26 78.49,18.26 93.73,18.26 108.97,18.26 124.21,18.26 17.53,18.26 32.77,18.26 48.01,18.26
NF5  (via drill 0.9 pad 1.78)
  Bottom 0.254: U$15.6 17.53,54.46 32.77,54.46 | 32.77,54.46 U$13.6 | 48.01,54.46 U$11.6 | 32.77,54.46 48.01,54.46 | 124.21,54.46 U$1.6 | 63.25,54.46 U$9.6 | 48.01,54.46 63.25,54.46 | 78.49,54.46 U$7.6 | 63.25,54.46 78.49,54.46 | 108.97,54.46 124.21,54.46 | 108.97,54.46 U$3.6 | 93.73,54.46 108.97,54.46 | 78.49,54.46 93.73,54.46 | 93.73,54.46 U$5.6 | 124.21,54.46 135.64,54.46 146.43,43.66 J1.C19
  other vias: 17.53,56.36 32.77,56.36 48.01,56.36 63.25,56.36 124.21,56.36 108.97,56.36 78.49,56.36 93.73,56.36
NF6  (via drill 0.9 pad 1.78)
  Bottom 0.254: 32.77,59.54 17.53,59.54 U$15.5 | 32.77,59.54 48.01,59.54 | 124.21,59.54 U$1.5 | 63.25,59.54 U$9.5 | 48.01,59.54 63.25,59.54 | 78.49,59.54 U$7.5 | 63.25,59.54 78.49,59.54 | 108.97,59.54 124.21,59.54 | 108.97,59.54 U$3.5 | 93.73,59.54 108.97,59.54 | 93.73,59.54 U$5.5 | 78.49,59.54 93.73,59.54 | 124.21,59.54 135.64,59.54 146.43,48.74 J1.C17 | 32.77,59.54 U$13.5 | 48.01,59.54 U$11.5
  other vias: 63.25,61.44 124.21,61.44 108.97,61.44 78.49,61.44 93.73,61.44 17.53,61.44 32.77,61.44 48.01,61.44
NF7  (via drill 0.9 pad 1.78)
  Bottom 0.254: 32.77,64.62 17.53,64.62 U$15.4 | 124.21,64.62 U$1.4 | 108.97,64.62 124.21,64.62 | 108.97,64.62 U$3.4 | 32.77,64.62 48.01,64.62 | 63.25,64.62 U$9.4 | 48.01,64.62 63.25,64.62 | 93.73,64.62 108.97,64.62 | 93.73,64.62 U$5.4 | 78.49,64.62 93.73,64.62 | 63.25,64.62 78.49,64.62 | 78.49,64.62 U$7.4 | 124.21,64.62 135.64,64.62 146.43,53.82 J1.C15 | 32.77,64.62 U$13.4 | 48.01,64.62 U$11.4
  other vias: 124.21,66.52 108.97,66.52 93.73,66.52 63.25,66.52 78.49,66.52 17.53,66.52 32.77,66.52 48.01,66.52
NF8  (via drill 0.9 pad 1.78)
  Bottom 0.254: U$15.3 17.53,69.7 32.77,69.7 | 32.77,69.7 U$13.3 | 124.21,69.7 U$1.3 | 108.97,69.7 124.21,69.7 | 108.97,69.7 U$3.3 | 48.01,69.7 U$11.3 | 32.77,69.7 48.01,69.7 | 63.25,69.7 U$9.3 | 48.01,69.7 63.25,69.7 | 93.73,69.7 108.97,69.7 | 93.73,69.7 U$5.3 | 78.49,69.7 93.73,69.7 | 63.25,69.7 78.49,69.7 | 78.49,69.7 U$7.3 | 124.21,69.7 135.64,69.7 146.43,58.9 J1.C13
  other vias: 17.53,71.6 124.21,71.6 32.77,71.6 48.01,71.6 108.97,71.6 93.73,71.6 63.25,71.6 78.49,71.6
NF9  (via drill 0.9 pad 1.78)
  Bottom 0.254: 25.15,35.41 9.91,35.41 U$16.13 | 25.15,35.41 40.39,35.41 | 40.39,35.41 55.63,35.41 | 55.63,35.41 U$10.13 | 55.63,35.41 70.87,35.41 86.11,35.41 | 86.11,35.41 U$6.13 | 86.11,35.41 101.35,35.41 | 101.35,35.41 U$4.13 | 101.35,35.41 116.59,35.41 | 116.59,35.41 U$2.13 | 116.59,35.41 141.99,35.41 146.43,30.96 J1.C24 | 40.39,35.41 U$12.13 | 25.15,35.41 U$14.13
  Bottom 0.305: 70.87,35.41 U$8.13
  other vias: 55.63,33.5 86.11,33.5 101.35,33.5 116.59,33.5 9.91,33.5 25.15,33.5 40.39,33.5
NF10  (via drill 0.9 pad 1.78)
  Bottom 0.254: 25.15,30.33 9.91,30.33 U$16.14 | 25.15,30.33 40.39,30.33 | 40.39,30.33 55.63,30.33 | 55.63,30.33 U$10.14 | 55.63,30.33 70.87,30.33 | 70.87,30.33 86.11,30.33 | 86.11,30.33 U$6.14 | 86.11,30.33 101.35,30.33 | 101.35,30.33 U$4.14 | 101.35,30.33 116.59,30.33 | 116.59,30.33 U$2.14 | 116.59,30.33 141.99,30.33 146.43,25.88 J1.C26 | 70.87,30.33 U$8.14 | 40.39,30.33 U$12.14 | 25.15,30.33 U$14.14
  other vias: 55.63,28.42 86.11,28.42 101.35,28.42 116.59,28.42 9.91,28.42 25.15,28.42 40.39,28.42
NF11  (via drill 0.9 pad 1.78)
  Bottom 0.254: 25.15,25.25 9.91,25.25 U$16.15 | 25.15,25.25 40.39,25.25 | 40.39,25.25 55.63,25.25 | 55.63,25.25 U$10.15 | 55.63,25.25 70.87,25.25 | 70.87,25.25 86.11,25.25 | 86.11,25.25 U$6.15 | 86.11,25.25 101.35,25.25 | 101.35,25.25 U$4.15 | 101.35,25.25 116.59,25.25 | 116.59,25.25 U$2.15 | 116.59,25.25 141.99,25.25 146.43,20.8 J1.C28 | 70.87,25.25 U$8.15 | 40.39,25.25 U$12.15 | 25.15,25.25 U$14.15
  other vias: 86.11,23.34 101.35,23.34 116.59,23.34 9.91,23.34 25.15,23.34 40.39,23.34
NF12  (via drill 0.9 pad 1.78)
  Bottom 0.254: 10.54,20.17 9.91,20.17 | 10.54,20.17 25.15,20.17 | 25.15,20.17 40.39,20.17 | 55.63,20.17 U$10.16 | 40.39,20.17 55.63,20.17 | 86.11,20.17 U$6.16 | 55.63,20.17 70.87,20.17 | 70.87,20.17 86.11,20.17 | 101.35,20.17 U$4.16 | 86.11,20.17 101.35,20.17 | 116.59,20.17 U$2.16 | 101.35,20.17 116.59,20.17 | 116.59,20.17 141.99,20.17 146.43,15.72 J1.C30 | 70.87,20.17 U$8.16 | 40.39,20.17 U$12.16 | 25.15,20.17 U$14.16 | U$16.16 9.91,19.53 10.54,20.17
  other vias: 86.11,18.26 101.35,18.26 116.59,18.26 9.91,18.26 25.15,18.26 40.39,18.26
NF13  (via drill 0.9 pad 1.78)
  Bottom 0.254: 25.15,58.27 9.91,58.27 U$16.6 | 25.15,58.27 40.39,58.27 | 40.39,58.27 55.63,58.27 | 55.63,58.27 U$10.6 | 116.59,58.27 U$2.6 | 101.35,58.27 116.59,58.27 | 101.35,58.27 U$4.6 | 55.63,58.27 70.87,58.27 | 70.87,58.27 86.11,58.27 | 86.11,58.27 101.35,58.27 | 86.11,58.27 U$6.6 | 116.59,58.27 134.37,58.27 146.43,46.2 J1.C18 | 25.15,58.27 U$14.6 | 40.39,58.27 U$12.6 | 70.87,58.27 U$8.6
  other vias: 116.59,56.36 55.63,56.36 101.35,56.36 86.11,56.36 9.91,56.36 25.15,56.36 40.39,56.36
NF14  (via drill 0.9 pad 1.78)
  Bottom 0.254: 25.15,63.35 9.91,63.35 U$16.5 | 25.15,63.35 40.39,63.35 | 40.39,63.35 55.63,63.35 | 55.63,63.35 U$10.5 | 116.59,63.35 U$2.5 | 101.35,63.35 U$4.5 | 101.35,63.35 116.59,63.35 | 55.63,63.35 70.87,63.35 | 70.87,63.35 86.11,63.35 | 86.11,63.35 101.35,63.35 | 86.11,63.35 U$6.5 | 116.59,63.35 134.37,63.35 146.43,51.28 J1.C16 | 25.15,63.35 U$14.5 | 40.39,63.35 U$12.5 | 70.87,63.35 U$8.5
  other vias: 116.59,61.44 55.63,61.44 101.35,61.44 86.11,61.44 9.91,61.44 25.15,61.44 40.39,61.44
NF15  (via drill 0.9 pad 1.78)
  Bottom 0.254: 25.15,68.43 9.91,68.43 U$16.4 | 25.15,68.43 40.39,68.43 | 40.39,68.43 55.63,68.43 | 55.63,68.43 U$10.4 | 116.59,68.43 U$2.4 | 101.35,68.43 U$4.4 | 101.35,68.43 116.59,68.43 | 55.63,68.43 70.87,68.43 | 70.87,68.43 86.11,68.43 | 86.11,68.43 101.35,68.43 | 86.11,68.43 U$6.4 | 116.59,68.43 134.37,68.43 146.43,56.36 J1.C14 | 25.15,68.43 U$14.4 | 40.39,68.43 U$12.4 | 70.87,68.43 U$8.4
  other vias: 116.59,66.52 55.63,66.52 101.35,66.52 86.11,66.52 9.91,66.52 25.15,66.52 40.39,66.52
NF16  (via drill 0.9 pad 1.78)
  Bottom 0.254: 116.59,73.51 U$2.3 | 25.15,73.51 9.91,73.51 U$16.3 | 25.15,73.51 40.39,73.51 | 101.35,73.51 U$4.3 | 101.35,73.51 116.59,73.51 | 86.11,73.51 101.35,73.51 | 86.11,73.51 U$6.3 | 40.39,73.51 55.63,73.51 | 55.63,73.51 U$10.3 | 55.63,73.51 70.87,73.51 | 70.87,73.51 86.11,73.51 | 116.59,73.51 134.37,73.51 146.43,61.44 J1.C12 | 25.15,73.51 U$14.3 | 40.39,73.51 U$12.3 | 70.87,73.51 U$8.3
  other vias: 116.59,71.6 101.35,71.6 55.63,71.6 86.11,71.6 9.91,71.6 25.15,71.6 40.39,71.6
S$121  (via drill 0.9 pad 1.78)
  Bottom 0.406: v116.59,48.74 119.13,51.28 v124.21,51.28
S$127  (via drill 0.9 pad 1.78)
  Bottom 0.406: v116.59,79.22 v124.21,79.22
S$139  (via drill 0.9 pad 1.78)
  Bottom 0.406: v108.97,51.28 103.89,51.28 v101.35,48.74
S$140  (via drill 0.9 pad 1.78)
  Bottom 0.406: v108.97,48.74 111.51,51.28 v116.59,51.28
S$163  (via drill 0.9 pad 1.78)
  Bottom 0.406: v101.35,79.22 v108.97,79.22
S$173  (via drill 0.9 pad 1.78)
  Bottom 0.406: v93.73,51.28 88.65,51.28 v86.11,48.74
S$174  (via drill 0.9 pad 1.78)
  Bottom 0.406: v93.73,48.74 96.27,51.28 v101.35,51.28
S$197  (via drill 0.9 pad 1.78)
  Bottom 0.406: v86.11,79.22 v93.73,79.22
S$207  (via drill 0.9 pad 1.78)
  Bottom 0.406: v78.49,51.28 73.41,51.28 v70.87,48.74
S$208  (via drill 0.9 pad 1.78)
  Bottom 0.406: v78.49,48.74 81.03,51.28 v86.11,51.28
S$231  (via drill 0.9 pad 1.78)
  Bottom 0.406: v70.87,79.22 v78.49,79.22
S$241  (via drill 0.9 pad 1.78)
  Bottom 0.406: v63.25,51.28 58.17,51.28 v55.63,48.74
S$242  (via drill 0.9 pad 1.78)
  Bottom 0.406: v63.25,48.74 65.79,51.28 v70.87,51.28
S$265  (via drill 0.9 pad 1.78)
  Bottom 0.406: v55.63,79.22 v63.25,79.22
S$275  (via drill 0.9 pad 1.78)
  Bottom 0.406: v48.01,51.28 42.93,51.28 v40.39,48.74
S$276  (via drill 0.9 pad 1.78)
  Bottom 0.406: v48.01,48.74 50.55,51.28 v55.63,51.28
S$299  (via drill 0.9 pad 1.78)
  Bottom 0.406: v40.39,79.22 v48.01,79.22
S$309  (via drill 0.9 pad 1.78)
  Bottom 0.406: v32.77,51.28 27.69,51.28 v25.15,48.74
S$310  (via drill 0.9 pad 1.78)
  Bottom 0.406: v32.77,48.74 35.31,51.28 v40.39,51.28
S$333  (via drill 0.9 pad 1.78)
  Bottom 0.406: v25.15,79.22 v32.77,79.22
S$343  (via drill 0.9 pad 1.78)
  Bottom 0.406: v17.53,51.28 12.45,51.28 v9.91,48.74
S$344  (via drill 0.9 pad 1.78)
  Bottom 0.406: v17.53,48.74 20.07,51.28 v25.15,51.28
S$384  (via drill 0.9 pad 1.78)
  Bottom 0.406: v9.91,79.22 v17.53,79.22
(copper drawn outside any net)
  shapes: Bottom area x129

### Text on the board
Bottom: 8 | 7 | 6 | 5 | 4 | 3 | 2 | 1 | LP-AMUX-BPa
Document: +12V | +8V | Audio | 8 | Audio | 7 | Audio | 6 | Audio | 5 | Audio | 4 | Audio | 3 | Audio | 2 | Audio | 1 | NF | 16 | NF | 8 | NF | 15 | NF | 7 | NF | 14 | NF | 6 | NF | 13 | NF | 5 | DA | EN | CL | NF | 9 | NF | 1 | NF | 10 | NF | 2 | NF | 11 | NF | 3 | NF | 12 | NF | 4 | GND
tDocu: EIN | EIN | EIN | EIN | EIN | EIN | EIN | EIN | BUS | BUS | BUS | BUS | BUS | BUS | BUS | BUS | BUS | BUS | BUS | BUS | BUS | BUS | BUS | BUS | Audio Multiplexer Basis-Platine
